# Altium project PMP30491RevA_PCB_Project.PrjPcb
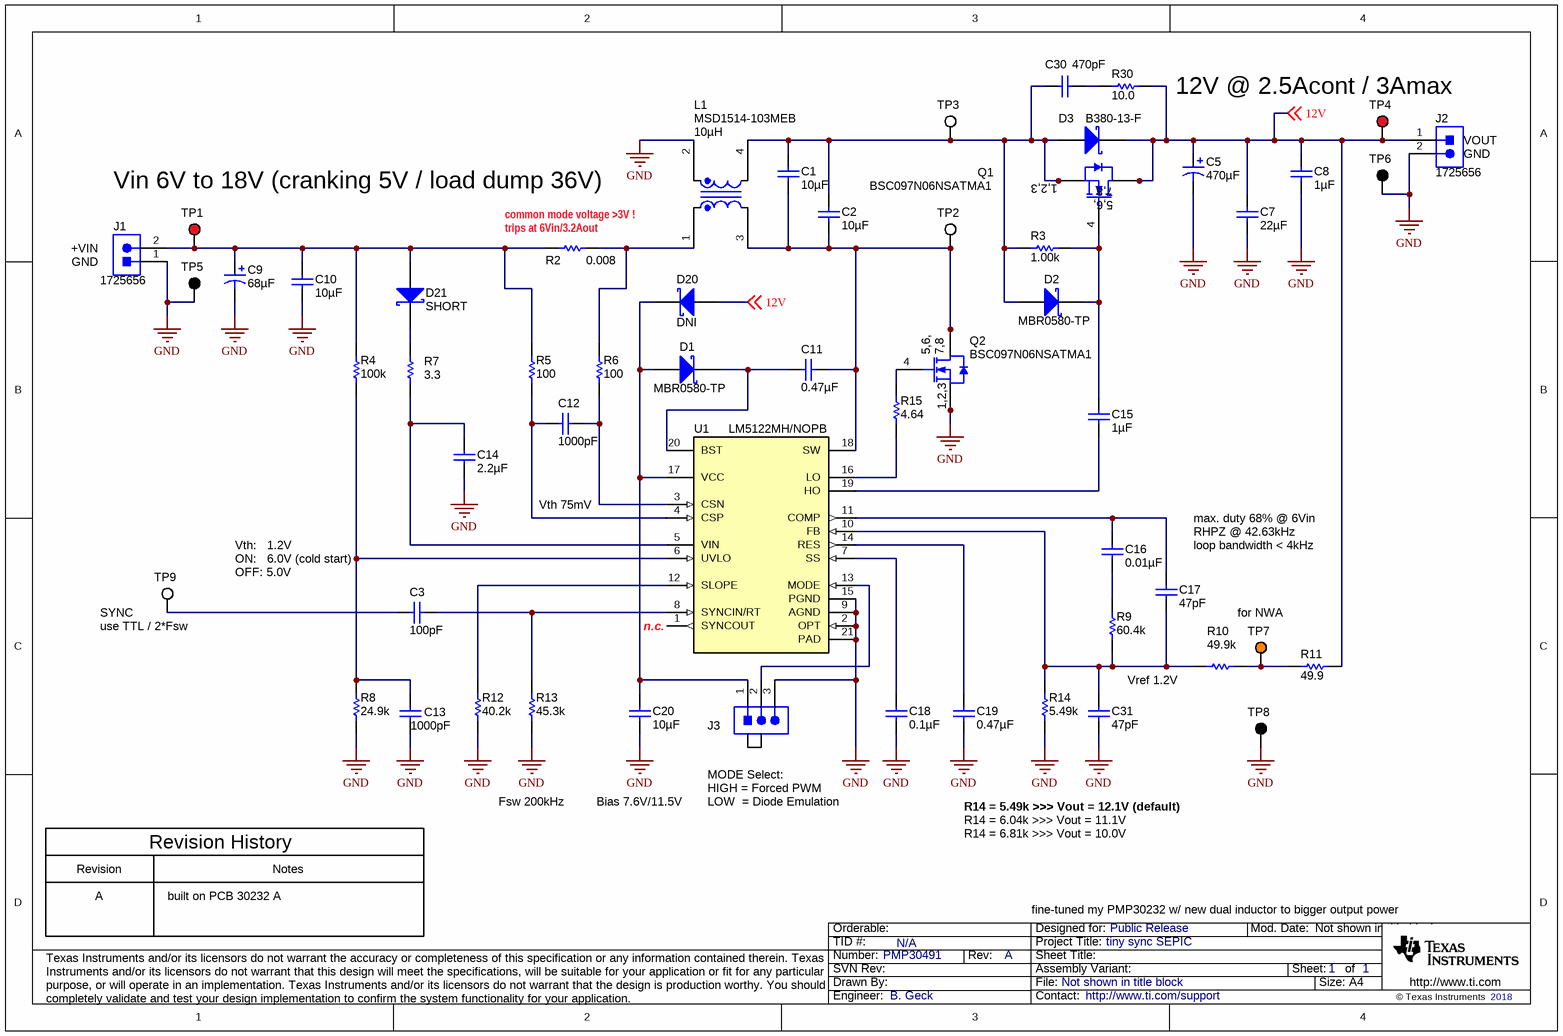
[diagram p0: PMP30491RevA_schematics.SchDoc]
CopyrightYear: 2018; PCB_Layout: B. Geck; PCB_Rev: A; PRJ_Customer: Public Release; PRJ_Engineer: B. Geck; PRJ_Number: PMP30491; PRJ_Title: tiny sync SEPIC; SCH_Rev: A; TechSupport: http://www.ti.com/support; TID: N/A
1 sheet, 56 parts. Net scope: global (net labels, ports and power ports of the same name join across sheets).

## Sheet PMP30491RevA_schematics.SchDoc
size A4; Date: Not shown in title block; ApprovedBy: Not shown in title block; CheckedBy: Not shown in title block; Author: Not shown in title block; CompanyName: Not shown in title block; Engineer: Not shown in title block; Organization: Not shown in title block; Address1: Not shown in title block; Address2: Not shown in title block; Address3: Not shown in title block; Address4: Not shown in title block; DocumentNumber: 1; Revision: Use project parameter SCH_Rev; SheetNumber: 1; SheetTotal: 1; PageSetup: Record=PageOptions¦CenterHorizontal=True¦CenterVertical=True¦PrintScale=0.94¦XCorrection=1.00¦YCorrection=1.00¦PrintKind=0¦BorderSize=5000000¦LeftOffset=0¦BottomOffset=0¦Orientation=2¦PaperLength=1000¦PaperWidth=1000¦Scale=100¦PaperSource=15¦PrintQuality=600¦MediaType=1¦DitherType=10¦PrintScaleMode=1¦PaperKind=Letter

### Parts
C1  ValueDisplayed: 10µF  [1210_270]  (hidden comment: GRM32ER71J106KA12L)
C2  ValueDisplayed: 10µF  [1210_270]  (hidden comment: GRM32ER71J106KA12L)
C3  ValueDisplayed: 100pF  [0603]  (hidden comment: GRM1885C1H101JA01D)
C5  ValueDisplayed: 470µF  [CAPSMT_62_JC0]  (hidden comment: 16SVPE470M)
C7  ValueDisplayed: 22µF  [1210_270]  (hidden comment: GRM32ER71E226KE15L)
C8  ValueDisplayed: 1µF  [0603]  (hidden comment: GRM188R71E105KA12D)
C9  ValueDisplayed: 68µF  [SM_RADIAL_10BMM]  (hidden comment: EEHZC1J680P)
C10  ValueDisplayed: 10µF  [1210_270]  (hidden comment: GRM32ER71J106KA12L)
C11  ValueDisplayed: 0.47µF  [0603]  (hidden comment: GRM188R71E474KA12D)
C12  ValueDisplayed: 1000pF  [0603]  (hidden comment: GRM188R71H102KA01D)
C13  ValueDisplayed: 1000pF  [0603]  (hidden comment: GRM188R71H102KA01D)
C14  ValueDisplayed: 2.2µF  [1206_190]  (hidden comment: GRM31CR72A225KA73L)
C15  ValueDisplayed: 1µF  [0603]  (hidden comment: C1608X7R1C105K080AC)
C16  ValueDisplayed: 0.01µF  [0603]  (hidden comment: GRM188R71H103KA01D)
C17  ValueDisplayed: 47pF  [0603]  (hidden comment: GRM1885C1H470JA01D)
C18  ValueDisplayed: 0.1µF  [0603]  (hidden comment: C1608X7R1H104K080AA)
C19  ValueDisplayed: 0.47µF  [0603]  (hidden comment: GRM188R71E474KA12D)
C20  ValueDisplayed: 10µF  [1206_180]  (hidden comment: GRM31CR71E106KA12L)
C30  ValueDisplayed: 470pF  [0805_HV]  (hidden comment: 08051C471KAT2A)
C31  ValueDisplayed: 47pF  [0603]  (hidden comment: GRM1885C1H470JA01D)
D1  MBR0580-TP  [SOD-123]
D2  MBR0580-TP  [SOD-123]
D3  B380-13-F  [SMC]
D20  DNI  [SOD-123]
D21  SHORT  [SOD-123]
J1  1725656  [CONN_1725656]
J2  1725656  [CONN_1725656]
J3  PEC03SAAN  [CONN_PEC03SAAN]  (value not drawn)
L1  MSD1514-103MEB  ValueDisplayed: 10µH  [MSD1514]
Q1  BSC097N06NSATMA1  [PG-TDSON-8]
Q2  BSC097N06NSATMA1  [PG-TDSON-8]
R2  ValueDisplayed: 0.008  [1206]  (hidden comment: WSL12068L000FEA)
R3  value 1.00k  [0603]  (hidden comment: CRCW06031K00FKEA)
R4  ValueDisplayed: 100k  [0603]  (hidden comment: CRCW0603100KFKEA)
R5  value 100  [0603]  (hidden comment: ERJ-3GEY0R00V)
R6  value 100  [0603]  (hidden comment: ERJ-3GEY0R00V)
R7  value 3.3  [0603]  (hidden comment: CRCW06033R30JNEA)
R8  ValueDisplayed: 24.9k  [0603]  (hidden comment: CRCW060324K9FKEA)
R9  ValueDisplayed: 60.4k  [0603]  (hidden comment: CRCW060360K4FKEA)
R10  value 49.9k  [0603]  (hidden comment: CRCW060349K9FKEA)
R11  ValueDisplayed: 49.9  [0603]  (hidden comment: CRCW060349R9FKEA)
R12  ValueDisplayed: 40.2k  [0603]  (hidden comment: CRCW060340K2FKEA)
R13  ValueDisplayed: 45.3k  [0603]  (hidden comment: CRCW060345K3FKEA)
R14  ValueDisplayed: 5.49k  [0603]  (hidden comment: CRCW06035K49FKEA)
R15  ValueDisplayed: 4.64  [0603]  (hidden comment: CRCW06034R64FKEA)
R30  ValueDisplayed: 10.0  [1206]  (hidden comment: PHP01206E10R0BST5)
TP1  5000  [Keystone5000]  (value not drawn)
TP2  5002  [Keystone5002]  (value not drawn)
TP3  5002  [Keystone5002]  (value not drawn)
TP4  5000  [Keystone5000]  (value not drawn)
TP5  5001  [Keystone5001]  (value not drawn)
TP6  5001  [Keystone5001]  (value not drawn)
TP7  5003  [Keystone5003]  (value not drawn)
TP8  5001  [Keystone5001]  (value not drawn)
TP9  5002  [Keystone5002]  (value not drawn)
U1  LM5122MH/NOPB  [PWP0020A_N]

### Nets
GND: C5.2(-) C7.2 C8.2 C9.2(-) C10.2 C13.2 C14.2 C18.2 C19.1 C20.2 C31.2 J1.1 J2.2 J3.3 L1.2 Q2.1(S) Q2.2(S) Q2.3(S) R8.1 R12.1 R13.1 R14.1 TP5.1 TP6.1 TP8.1 U1.2(OPT) U1.9(AGND) U1.15(PGND) U1.21(PAD)
12V: C5.1(+) C7.1 C8.1 D3.1(K) D20.2(A) J2.1 Q1.5(D) Q1.6(D) Q1.7(D) Q1.8(D) Q1.9(D) R11.2 R30.2 TP4.1 ; off-sheet 12V
NetC1_1: C1.1 C2.1 C30.2 D2.2(A) D3.2(A) L1.4 Q1.1(S) Q1.2(S) Q1.3(S) R3.1 TP3.1
NetC1_2: C1.2 C2.2 C11.2 L1.3 Q2.5(D) Q2.6(D) Q2.7(D) Q2.8(D) Q2.9(D) TP2.1 U1.18(SW)
NetC3_1: C3.1 R13.2 U1.8(SYNCIN/RT)
NetC3_2: C3.2 TP9.1
NetC9_1: C9.1(+) C10.1 D21.2(A) J1.2 R2.1 R4.2 R5.2 TP1.1
NetC11_1: C11.1 D1.1(K) U1.20(BST)
NetC12_1: C12.1 R6.1 U1.3(CSN)
NetC12_2: C12.2 R5.1 U1.4(CSP)
NetC13_1: C13.1 R4.1 R8.2 U1.6(UVLO)
NetC14_1: C14.1 R7.2 U1.5(VIN)
NetC15_1: C15.1 D2.1(K) Q1.4(G) R3.2
NetC15_2: C15.2 U1.19(HO)
NetC16_1: C16.1 C17.1 U1.11(COMP)
NetC16_2: C16.2 R9.2
NetC17_2: C17.2 C31.1 R9.1 R10.1 R14.2 U1.10(FB)
NetC18_1: C18.1 U1.7(SS)
NetC19_2: C19.2 U1.14(RES)
NetC20_1: C20.1 D1.2(A) D20.1(K) J3.1 U1.17(VCC)
NetC30_1: C30.1 R30.1
NetD21_1: D21.1(K) R7.1
NetJ3_2: J3.2 U1.13(MODE)
NetL1_1: L1.1 R2.2 R6.2
NetQ2_4: Q2.4(G) R15.2
NetR10_2: R10.2 R11.1 TP7.1
NetR12_2: R12.2 U1.12(SLOPE)
NetR15_1: R15.1 U1.16(LO)

Not connected (* = marked no-connect by the designer): U1 1(SYNCOUT)

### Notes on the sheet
- 12V @ 2.5Acont / 3Amax
- Vin 6V to 18V (cranking 5V / load dump 36V)
- (near J2) VOUT
- (near J2) GND
- (near J1) +VIN
- common mode voltage >3V !
- (near R2) trips at 6Vin/3.2Aout
- (near J1) GND
- Vth 75mV
- max. duty 68% @ 6Vin
- ON:   6.0V (cold start)
- Vth:   1.2V
- OFF: 5.0V
- RHPZ @ 42.63kHz
- (near C17) loop bandwidth < 4kHz
- (near TP9) SYNC
- (near TP9) use TTL / 2*Fsw
- (near U1) n.c.
- for NWA
- Vref 1.2V
- HIGH = Forced PWM
- MODE Select:
- Revision History
- Fsw 200kHz
- Bias 7.6V/11.5V
- LOW  = Diode Emulation
- R14 = 6.04k >>> Vout = 11.1V
- R14 = 5.49k >>> Vout = 12.1V (default)
- R14 = 6.81k >>> Vout = 10.0V
- Revision
- A
- built on PCB 30232 A
- Notes
- fine-tuned my PMP30232 w/ new dual inductor to bigger output power

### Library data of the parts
C1 C2 C10 = GRM32ER71J106KA12L: CAP, CERM, 10 µF, 63 V, +/- 10%, X7R, 1210; Manufacturer: MuRata; Polarized: N; CompType: Capacitor; Value: 10uF; U/M: EA; Cap_F: 0.00001; Tolerance_%: 10; Value1: Unknown; VDC_V: 63; Value2: 63V; TaMin_C: -55; TaMax_C: 125; Cap_Case: 1210; SizeArea_mm2: 8; SizeAreaWB_mm2: 14.7; SizeX_mm: 3.2; SizeY_mm: 2.5; SizeZ_mm: 2.7; AEC Category: Q200
C3 = GRM1885C1H101JA01D: CAP, CERM, 100 pF, 50 V, +/- 5%, C0G/NP0, 0603; Manufacturer: MuRata; Polarized: N; CompType: Capacitor; Value: 100pF; U/M: EA; Cap_F: 0.0000000001; Tolerance_%: 5; Value1: Unknown; VDC_V: 50; Value2: 50V; TaMin_C: -55; TaMax_C: 125; SizeArea_mm2: 1.28; SizeAreaWB_mm2: 4.68; SizeX_mm: 1.6; SizeY_mm: 0.8; SizeZ_mm: 1; AEC Category: Q200
C5 = 16SVPE470M: CAP, Aluminum Polymer, 470 µF, 16 V, +/- 20%, 0.01 ohm, JC0 SMD; Manufacturer: Panasonic; Polarized: Y; CompType: Capacitor; Value: 470uF; U/M: EA; Cap_F: 0.00047; Tolerance_%: 20; VDC_V: 16; Value2: 16V; ESR_ohm: 0.01; IRMS_A: 6.1; TaMin_C: -55; TaMax_C: 105; SizeAreaWB_mm2: 156.25; SizeArea_mm2: 110.25; SizeX_mm: 10.5; SizeZ_mm: 12.5; AEC Category: Q200
C7 = GRM32ER71E226KE15L: CAP, CERM, 22 µF, 25 V, +/- 10%, X7R, 1210; Manufacturer: MuRata; Polarized: N; CompType: Capacitor; Value: 22uF; U/M: EA; Cap_F: 0.000022; Tolerance_%: 10; Value1: Unknown; VDC_V: 25; Value2: 25V; TaMin_C: -55; TaMax_C: 125; Cap_Case: 1210; SizeArea_mm2: 8; SizeAreaWB_mm2: 14.7; SizeX_mm: 3.2; SizeY_mm: 2.5; SizeZ_mm: 2.7; AEC Category: Q200
C8 = GRM188R71E105KA12D: CAP, CERM, 1 µF, 25 V, +/- 10%, X7R, 0603; Manufacturer: MuRata; Polarized: N; CompType: Capacitor; Value: 1uF; U/M: EA; Cap_F: 0.000001; Tolerance_%: 10; Value1: Unknown; VDC_V: 25; Value2: 25V; TaMin_C: -55; TaMax_C: 125; SizeArea_mm2: 1.28; SizeAreaWB_mm2: 4.68; SizeX_mm: 1.6; SizeY_mm: 0.8; SizeZ_mm: 1; AEC Category: Q200
C9 = EEHZC1J560P: CAP, Polymer Hybrid, 68 µF, 63 V, +/- 20%, 30 ohm, 10x10 SMD; Manufacturer: Panasonic; Polarized: Y; CompType: Capacitor; Value: 68uF; U/M: EA; Cap_F: 0.000068; Tolerance_%: 20; Value1: 30 MilliOhm; VDC_V: 63; Value2: 63V; ESR_ohm: 0.03; IRMS_A: 1.4; TaMin_C: -55; TaMax_C: 125; SizeAreaWB_mm2: 159.9; SizeArea_mm2: 113.3; SizeX_mm: 11; SizeY_mm: 10.3; SizeZ_mm: 10.2; AEC Category: Q200
C11 C19 = GRM188R71E474KA12D: CAP, CERM, 0.47uF, 25V, +/-10%, X7R, 0603; Manufacturer: MuRata; Polarized: N; CompType: Capacitor; U/M: EA; Cap_F: 0.00000047; Tolerance_%: 10; Value1: Unknown; VDC_V: 25; TaMin_C: -55; TaMax_C: 125
C12 C13 = GRM188R71H102KA01D: CAP, CERM, 1000pF, 50V, +/-10%, X7R, 0603; Manufacturer: MuRata; Polarized: N; CompType: Capacitor; U/M: EA; Cap_F: 0.000000001; Tolerance_%: 10; Value1: Unknown; VDC_V: 50; TaMin_C: -55; TaMax_C: 125
C14 = GRM31CR72A225KA73L: CAP, CERM, 2.2 µF, 100 V, +/- 10%, X7R, 1206_190; Manufacturer: MuRata; Polarized: N; CompType: Capacitor; Value: 2.2uF; U/M: EA; Cap_F: 0.0000022; Tolerance_%: 10; Value1: Unknown; VDC_V: 100; Value2: 100V; TaMin_C: -55; TaMax_C: 125; Cap_Case: 1206; SizeArea_mm2: 5.12; SizeAreaWB_mm2: 10.92; SizeX_mm: 3.2; SizeY_mm: 1.6; SizeZ_mm: 1.9; AEC Category: Q200
C15 = C1608X7R1C105K080AC: CAP, CERM, 1 µF, 16 V, +/- 10%, X7R, 0603; Manufacturer: TDK; Polarized: N; CompType: Capacitor; Value: 1uF; U/M: EA; Cap_F: 0.000001; Tolerance_%: 10; ESR_ohm: 0.0057; Value1: 0.0057 ohm; VDC_V: 16; Value2: 16V; TaMin_C: -55; TaMax_C: 125; SizeArea_mm2: 1.28; SizeAreaWB_mm2: 4.68; SizeX_mm: 1.6; SizeY_mm: 0.8; SizeZ_mm: 1; AEC Category: Q200
C16 = GRM188R71H103KA01D: CAP, CERM, 0.01 µF, 50 V, +/- 10%, X7R, 0603; Manufacturer: MuRata; Polarized: N; CompType: Capacitor; Value: 0.01uF; U/M: EA; Cap_F: 0.00000001; Tolerance_%: 10; Value1: Unknown; VDC_V: 50; Value2: 50V; TaMin_C: -55; TaMax_C: 125; SizeArea_mm2: 1.28; SizeAreaWB_mm2: 4.68; SizeX_mm: 1.6; SizeY_mm: 0.8; SizeZ_mm: 1; AEC Category: Q200
C17 C31 = GRM1885C1H470JA01D: CAP, CERM, 47 pF, 50 V, +/- 5%, C0G/NP0, 0603; Manufacturer: MuRata; Polarized: N; CompType: Capacitor; Value: 47pF; U/M: EA; Cap_F: 0.000000000047; Tolerance_%: 5; Value1: Unknown; VDC_V: 50; Value2: 50V; TaMin_C: -55; TaMax_C: 125; SizeArea_mm2: 1.28; SizeAreaWB_mm2: 4.68; SizeX_mm: 1.6; SizeY_mm: 0.8; SizeZ_mm: 1; AEC Category: Q200
C18 = C1608X7R1H104K080AA: CAP, CERM, 0.1 µF, 50 V, +/- 10%, X7R, 0603; Manufacturer: TDK; Polarized: N; CompType: Capacitor; Value: 0.1uF; U/M: EA; Cap_F: 0.0000001; Tolerance_%: 10; ESR_ohm: 0.0296; Value1: 0.0296 ohm; VDC_V: 50; Value2: 50V; IRMS_A: 0.97199; TaMin_C: -55; TaMax_C: 125; SizeArea_mm2: 1.28; SizeAreaWB_mm2: 4.68; SizeX_mm: 1.6; SizeY_mm: 0.8; SizeZ_mm: 1; AEC Category: Q200
C20 = GRM31CR71E106KA12L: CAP, CERM, 10 µF, 25 V, +/- 10%, X7R, 1206; Manufacturer: MuRata; Polarized: N; CompType: Capacitor; Value: 10uF; U/M: EA; Cap_F: 0.00001; Tolerance_%: 10; Value1: Unknown; VDC_V: 25; Value2: 25V; TaMin_C: -55; TaMax_C: 125; Cap_Case: 2220; SizeArea_mm2: 5.12; SizeAreaWB_mm2: 10.92; SizeX_mm: 3.2; SizeY_mm: 1.6; SizeZ_mm: 1.8; AEC Category: Q200
C30 = 08051C471KAT2A: CAP, CERM, 470 pF, 100 V, +/- 10%, X7R, 0805; Manufacturer: AVX; Polarized: N; CompType: Capacitor; Value: 470pF; U/M: EA; Cap_F: 0.00000000047; Tolerance_%: 10; ESR_ohm: 0.454; Value1: 0.454 ohm; VDC_V: 100; Value2: 100V; TaMin_C: -55; TaMax_C: 125; Cap_Case: 0805; SizeArea_mm2: 2.5; SizeAreaWB_mm2: 6.75; SizeX_mm: 2; SizeY_mm: 1.25; SizeZ_mm: 1.45; AEC Category: Q200
D1 D2 D20 D21 = MBR0580-TP: Diode, Schottky, 80 V, 0.5 A, SOD-123; Manufacturer: Micro Commercial Components; U/M: EA; Vf_V: 0.8; Value: 80V; Value1: 0.5A; Value2: 0.8V; Io_A: 0.5; Vr_V: 80; TJmax_C: 150; SizeAreaWB_mm2: 13.095; SizeArea_mm2: 6.545; SizeX_mm: 3.85; SizeY_mm: 1.7; SizeZ_mm: 1.35; AEC Category: Q101
D3 = B380-13-F: Diode, Schottky, 80 V, 3 A, SMC; Manufacturer: Diodes Inc.; U/M: EA; Vf_V: 0.79; Value: 80V; Value1: 3A; Value2: 0.79V; Io_A: 3; Vr_V: 80; TJmax_C: 125; RJC_CperW: 10; SizeAreaWB_mm2: 83.2686; SizeArea_mm2: 50.5686; SizeX_mm: 8.13; SizeY_mm: 6.22; SizeZ_mm: 2.6; AEC Category: Q101
J1 J2 = 1725656: Terminal Block, 100mil, 2x1, 6A, 63V, TH; Manufacturer: Phoenix Contact; SymbolCreator: a0412235
J3 = PEC03SAAN: Header, 100mil, 3x1, Tin, TH; Manufacturer: Sullins Connector Solutions; SymbolCreator: a0799628; U/M: EA
L1 = MSD1514-103MEB: Coupled inductor, 10 µH, 16.2 A, 0.015 ohm, SMD; Manufacturer: Coilcraft; SymbolCreator: a0412235; SizeAreaWB_mm2: 289; SizeArea_mm2: 225; SizeX_mm: 15; SizeZ_mm: 14.2; Value: 10uH; Ind_H: 10.0E-6; DCR_ohm: 0.015; AEC Category: Q200; AEC Qualified: N
Q1 Q2 = BSC097N06NSATMA1: MOSFET, N-CH, 60 V, 46 A, PG-TDSON-8; Manufacturer: Infineon Technologies; Alternate Manufacturer: None; U/M: EA; ChType: N; Value: 60V; VdsMax_V: 60; Value1: ? ohm; Value2: 12 nC; QgTyp_nC: 12; Vgs_V: 20; IdsMax_A: 46; SizeAreaWB_mm2: 55.131; SizeArea_mm2: 29.351; SizeX_mm: 5.99; SizeY_mm: 4.9; SizeZ_mm: 1.12; AEC Category: Q101
R2 = WSL12068L000FEA: RES, 0.008, 1%, 0.25 W, AEC-Q200 Grade 0, 1206; Manufacturer: Vishay-Dale; CompType: Resistor; Value: 0.008; Value_Code: 8L000; Tolerance_%: 1; Power_W: 0.25; Value2: 0.25W; TempCo: 75 ppm/C; SizeArea_mm2: 5.12; SizeX_mm: 3.2; SizeY_mm: 1.6; SizeZ_mm: 1.35; EIA_Code: E96; U/M: EA; AEC Category: Q200; AEC Qualified: Y; AEC Grade: 0
R3 = CRCW06031K00FKEA: RES, 1.00k ohm, 1%, 0.1W, 0603; Manufacturer: Vishay-Dale; CompType: Resistor; Res_ohm: 1000; Value_Code: 1k00; Tolerance_%: 1; Power_W: 0.1; VDC_V: 75; TempCo: 100 ppm/C; EIA_Code: E96; U/M: EA
R4 = CRCW0603100KFKEA: RES, 100 k, 1%, 0.1 W, 0603; Manufacturer: Vishay-Dale; CompType: Resistor; Value: 100k; Res_ohm: 100000; Tolerance_%: 1; Power_W: 0.1; Value2: 0.1W; VDC_V: 75; TempCo: 100 ppm/C; SizeArea_mm2: 1.28; SizeX_mm: 1.6; SizeY_mm: 0.8; EIA_Code: E96; U/M: EA; AEC Category: Q200
R5 R6 = ERJ-3GEY0R00V: RES, 0 ohm, 5%, 0.1W, 0603; Manufacturer: Panasonic; CompType: Resistor; Res_ohm: 0; Value_Code: 0000; Tolerance_%: 5; Power_W: 0.1; VDC_V: 50; TempCo: 600 ppm/C; EIA_Code: E24; U/M: EA
R7 = CRCW06033R30JNEA: RES, 3.3 ohm, 5%, 0.1W, 0603; Manufacturer: Vishay-Dale; CompType: Resistor; Value_Code: 3R30; Tolerance_%: 5; Power_W: 0.1; VDC_V: 75; TempCo: 200 ppm/C; EIA_Code: E24; U/M: EA
R8 = CRCW060324K9FKEA: RES, 24.9 k, 1%, 0.1 W, 0603; Manufacturer: Vishay-Dale; CompType: Resistor; Value: 24.9k; Res_ohm: 24900; Value_Code: 24k9; Tolerance_%: 1; Power_W: 0.1; Value2: 0.1W; VDC_V: 75; TempCo: 100 ppm/C; SizeArea_mm2: 1.28; SizeX_mm: 1.6; SizeY_mm: 0.8; EIA_Code: E96; U/M: EA; AEC Category: Q200
R9 = CRCW060360K4FKEA: RES, 60.4 k, 1%, 0.1 W, 0603; Manufacturer: Vishay-Dale; CompType: Resistor; Value: 60.4k; Res_ohm: 60400; Value_Code: 60k4; Tolerance_%: 1; Power_W: 0.1; Value2: 0.1W; VDC_V: 75; TempCo: 100 ppm/C; SizeArea_mm2: 1.28; SizeX_mm: 1.6; SizeY_mm: 0.8; EIA_Code: E96; U/M: EA; AEC Category: Q200
R10 = CRCW060349K9FKEA: RES, 49.9k ohm, 1%, 0.1W, 0603; Manufacturer: Vishay-Dale; CompType: Resistor; Res_ohm: 49900; Value_Code: 49k9; Tolerance_%: 1; Power_W: 0.1; VDC_V: 75; TempCo: 100 ppm/C; EIA_Code: E96; U/M: EA
R11 = CRCW060349R9FKEA: RES, 49.9, 1%, 0.1 W, 0603; Manufacturer: Vishay-Dale; CompType: Resistor; Value: 49.9; Value_Code: 49R9; Tolerance_%: 1; Power_W: 0.1; Value2: 0.1W; VDC_V: 75; TempCo: 100 ppm/C; EIA_Code: E96; U/M: EA
R12 = CRCW060340K2FKEA: RES, 40.2 k, 1%, 0.1 W, 0603; Manufacturer: Vishay-Dale; CompType: Resistor; Value: 40.2k; Res_ohm: 40200; Value_Code: 40k2; Tolerance_%: 1; Power_W: 0.1; Value2: 0.1W; VDC_V: 75; TempCo: 100 ppm/C; EIA_Code: E96; U/M: EA
R13 = CRCW060345K3FKEA: RES, 45.3 k, 1%, 0.1 W, 0603; Manufacturer: Vishay-Dale; CompType: Resistor; Value: 45.3k; Res_ohm: 45300; Value_Code: 45k3; Tolerance_%: 1; Power_W: 0.1; Value2: 0.1W; VDC_V: 75; TempCo: 100 ppm/C; SizeArea_mm2: 1.28; SizeX_mm: 1.6; SizeY_mm: 0.8; EIA_Code: E96; U/M: EA; AEC Category: Q200; Green_Lifecycle: Active; Green_REACh: Passed
R14 = CRCW06035K49FKEA: RES, 5.49 k, 1%, 0.1 W, 0603; Manufacturer: Vishay-Dale; CompType: Resistor; Value: 5.49k; Res_ohm: 5490; Value_Code: 5k49; Tolerance_%: 1; Power_W: 0.1; Value2: 0.1W; VDC_V: 75; TempCo: 100 ppm/C; SizeArea_mm2: 1.28; SizeX_mm: 1.6; SizeY_mm: 0.8; EIA_Code: E96; U/M: EA; AEC Category: Q200
R15 = CRCW06034R64FKEA: RES, 4.64, 1%, 0.1 W, 0603; Manufacturer: Vishay-Dale; CompType: Resistor; Value: 4.64; Value_Code: 4R64; Tolerance_%: 1; Power_W: 0.1; Value2: 0.1W; VDC_V: 75; TempCo: 100 ppm/C; SizeArea_mm2: 1.28; SizeX_mm: 1.6; SizeY_mm: 0.8; EIA_Code: E96; U/M: EA; AEC Category: Q200
R30 = PHP01206E10R0BST5: RES, 10.0, 0.1%, 1 W, 1206; Manufacturer: Vishay-Dale; CompType: Resistor; Value: 10.0; Res_ohm: 10; Value_Code: 10R0; Tolerance_%: 0.1; Power_W: 1; Value2: 1W; VDC_V: 100; TempCo: 25 ppm/C; SizeArea_mm2: 5.12; SizeX_mm: 3.2; SizeY_mm: 1.6; SizeZ_mm: 1.35; EIA_Code: E192; U/M: EA; AEC Category: Q200
TP1 TP4 = 5000: Test Point, Miniature, Red, TH; Manufacturer: Keystone; CompType: Test Point Loop; U/M: EA
TP2 TP3 TP9 = 5002: Test Point, Miniature, White, TH; Manufacturer: Keystone; CompType: Test Point Loop; ContactFinish: Silver
TP5 TP6 TP8 = 5001: Test Point, Miniature, Black, TH; Manufacturer: Keystone; CompType: Test Point Loop; U/M: EA
TP7 = 5003: Test Point, Miniature, Orange, TH; Manufacturer: Keystone; CompType: Test Point Loop; ContactFinish: Silver
U1 = LM5122MHX/NOPB: Wide Input Synchronous Boost Controller with Multiple Phase Capability, PWP0020A (TSSOP-20); Alternate Manufacturer: Texas Instruments; Alternate PartNumber: LM5122MHE/NOPB; SymbolCreator: a0411947; CompType: IC; U/M: EA; SizeArea_mm2: 41.6; SizeAreaWB_mm2: 71.4; SizeX_mm: 6.4; SizeY_mm: 6.5; SizeZ_mm: 1.2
